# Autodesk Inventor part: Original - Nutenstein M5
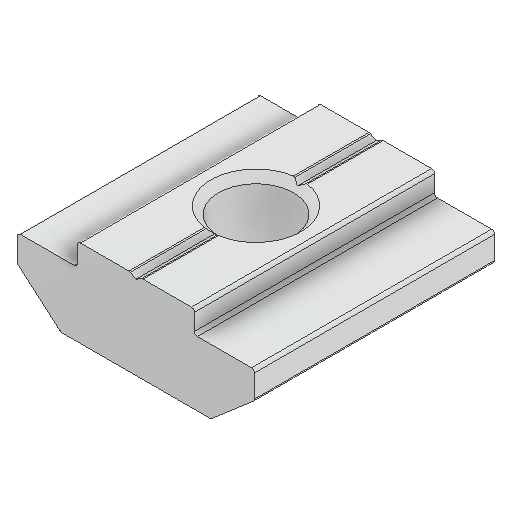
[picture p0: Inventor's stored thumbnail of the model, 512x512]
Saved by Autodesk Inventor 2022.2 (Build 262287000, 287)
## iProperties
Created: 2024-09
Part Number: Original - Nutenstein M5
Material: Generico
Document SubType Name: Modeling
Designer: 18907419
Density: 1 g/cm^3
Appearance: Default
Author: 18907419
Revision Number: ANY
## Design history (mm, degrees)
feature "Verrundung1"
node "Solido1"
